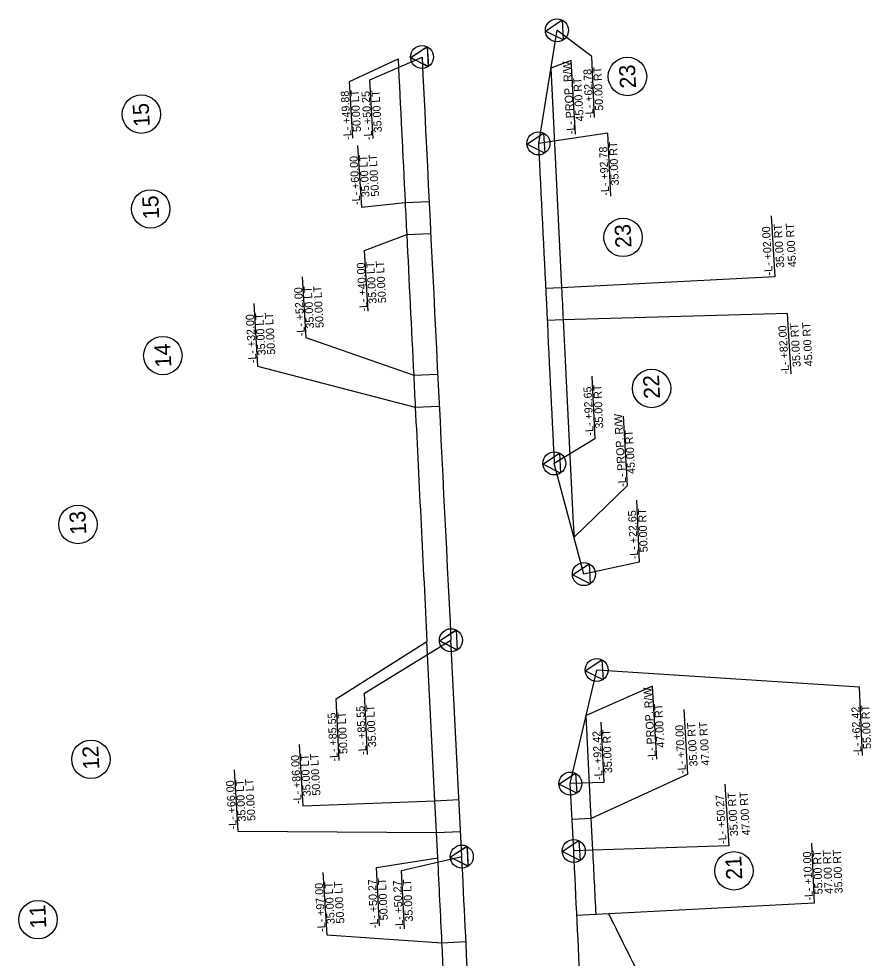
# Model space of a CAD drawing. Extents: x 2368169 to 2369183, y 801414 to 808542.
# Drawn here: x 2368559 to 2369092, y 803014 to 803601 of the extents above; entities that cross this region are included whole.
import ezdxf

# ---------------------------------------------------------------- set-up
doc = ezdxf.new("R2010")
doc.units = 0
for name, color, linetype in [('Prop Easement Construction', 7, 'Continuous'), ('Prop Easement Construction Station Offsets', 7, 'Continuous'), ('Prop Easement Permanent Drainage', 7, 'Continuous'), ('Prop Easement Permanent Drainage Station Offsets', 7, 'Continuous'), ('Prop Easement Permanent Drainage Utility', 7, 'Continuous'), ('Prop Easement Permanent Drainage Utility Station Offsets', 7, 'Continuous'), ('Prop Easement Permanent Utility', 7, 'Continuous'), ('Prop Easement Permanent Utility Station Offsets', 7, 'Continuous'), ('Prop Parcel Number CELL', 7, 'Continuous'), ('Prop Parcel Number Text', 7, 'Continuous'), ('Prop ROW Marker CELL', 7, 'Continuous'), ('Prop ROW RW Lines', 7, 'Continuous'), ('Prop ROW Station Offsets', 7, 'Continuous')]:
    doc.layers.add(name, color=color, linetype=linetype)

msp = doc.modelspace()

# ---------------------------------------------------------------- linework, layer by layer
at = {"layer": 'Prop Easement Construction'}
msp.add_line((2368916.67, 803101.18), (2368913.44, 803165.51), dxfattribs=at)
for centre, radius, start, end in [((2677047.33, 818679.94), 308526.21, 182.8071824, 182.8327013), ((2677047.33, 818679.94), 308526.21, 182.8364149, 182.8616691), ((2343687.36, 801815.32), 25262.05, 2.781389, 2.872893)]:
    msp.add_arc(centre, radius, start, end, dxfattribs=at)
at = {"layer": 'Prop Easement Construction Station Offsets'}
for points in [[(2368906.85, 803528.48), (2368904.06, 803574.6), (2368891.35, 803569.88)], [(2368936.52, 803352.45), (2368939.16, 803308.95), (2368905.86, 803276.84)], [(2368957.57, 803138.15), (2368954.8, 803183.74), (2368913.44, 803165.51)]]:
    msp.add_lwpolyline(points, dxfattribs=at)
at = {"layer": 'Prop Easement Permanent Drainage'}
for p, q in [((2368898.11, 803432.63), (2368888.12, 803432.14)), ((2368899.1, 803412.66), (2368889.11, 803412.16)), ((2368916.67, 803101.18), (2368904.69, 803100.57)), ((2368917.66, 803081.47), (2368916.67, 803101.18)), ((2368917.66, 803081.47), (2368905.68, 803080.87)), ((2368927.64, 803041.56), (2368907.66, 803040.59))]:
    msp.add_line(p, q, dxfattribs=at)
for centre, radius, start, end in [((2677047.33, 818679.94), 308526.21, 182.8327013, 182.8364149), ((2333618.27, 785468.75), 39440.53, 26.379142, 26.458672)]:
    msp.add_arc(centre, radius, start, end, dxfattribs=at)
at = {"layer": 'Prop Easement Permanent Drainage Station Offsets'}
for p, q in [((2369029.03, 803477.59), (2369031.33, 803439.43)), ((2369031.33, 803439.43), (2368898.11, 803432.63)), ((2368977.01, 803128.78), (2368974.58, 803169.22)), ((2368977.01, 803128.78), (2368916.67, 803101.18)), ((2369000.18, 803122.68), (2369002.5, 803084.13)), ((2369002.5, 803084.13), (2368917.66, 803081.47)), ((2369054.13, 803085.79), (2369055.96, 803048.33)), ((2369055.96, 803048.33), (2368927.64, 803041.56))]:
    msp.add_line(p, q, dxfattribs=at)
msp.add_lwpolyline([(2369041.5, 803378.85), (2369039.23, 803416.58), (2368899.1, 803412.66)], dxfattribs=at)
at = {"layer": 'Prop Easement Permanent Drainage Utility'}
for p, q in [((2368800.37, 803485.87), (2368815.35, 803486.61)), ((2368801.35, 803465.9), (2368816.33, 803466.63)), ((2368805.7, 803377.99), (2368820.68, 803378.73)), ((2368806.7, 803358.01), (2368821.68, 803358.75)), ((2368818.99, 803112.29), (2368833.97, 803113.05)), ((2368819.99, 803092.32), (2368818.99, 803112.29)), ((2368819.99, 803092.32), (2368834.98, 803093.07)), ((2368823.39, 803023.51), (2368838.37, 803024.23))]:
    msp.add_line(p, q, dxfattribs=at)
for centre, radius, start, end in [((2677047.33, 818679.94), 308621.21, 182.8219318, 182.8256454), ((2677047.33, 818679.94), 308621.21, 182.8419854, 182.845699), ((2343687.36, 801815.32), 25165.05, 2.706404, 2.75185)]:
    msp.add_arc(centre, radius, start, end, dxfattribs=at)
at = {"layer": 'Prop Easement Permanent Drainage Utility Station Offsets'}
for points in [[(2368770.71, 803521.54), (2368773.03, 803482.92), (2368800.37, 803485.87)], [(2368777.36, 803418.11), (2368775.09, 803455.86), (2368801.35, 803465.9)], [(2368736.09, 803439.51), (2368738.37, 803401.57), (2368805.7, 803377.99)], [(2368705.83, 803422.73), (2368708.18, 803383.67), (2368806.7, 803358.01)], [(2368734.07, 803147.38), (2368736.37, 803109.12), (2368818.99, 803112.29)], [(2368693.48, 803131.54), (2368695.78, 803093.28), (2368819.99, 803092.32)], [(2368749.02, 803067.51), (2368751.37, 803028.45), (2368823.39, 803023.51)]]:
    msp.add_lwpolyline(points, dxfattribs=at)
at = {"layer": 'Prop Easement Permanent Utility'}
for p, q in [((2368818.99, 803112.29), (2368814, 803211.71)), ((2368820.78, 803076.61), (2368819.99, 803092.32))]:
    msp.add_line(p, q, dxfattribs=at)
for centre, radius, start, end in [((2677047.33, 818679.94), 308621.21, 182.8052436, 182.8219318), ((2677047.33, 818679.94), 308621.21, 182.8256454, 182.8419854), ((2677047.33, 818679.94), 308621.21, 182.845699, 182.8728926), ((2343687.36, 801815.32), 25165.05, 2.75185, 2.872893)]:
    msp.add_arc(centre, radius, start, end, dxfattribs=at)
at = {"layer": 'Prop Easement Permanent Utility Station Offsets'}
for p, q in [((2368765.55, 803561.44), (2368795.95, 803575.66)), ((2368767.68, 803526.06), (2368765.55, 803561.44)), ((2368757.21, 803175.81), (2368814, 803211.71)), ((2368759.08, 803137.45), (2368757.21, 803175.81))]:
    msp.add_line(p, q, dxfattribs=at)
msp.add_lwpolyline([(2368784.34, 803034.08), (2368782.56, 803070.56), (2368820.78, 803076.61)], dxfattribs=at)
at = {"layer": 'Prop Parcel Number CELL'}
for p, q in [((2368939.26, 803564.6), (2368939.26, 803564.6)), ((2368635.62, 803541.07), (2368635.62, 803541.07)), ((2368641.47, 803481.9), (2368641.47, 803481.9)), ((2368936.54, 803464.08), (2368936.54, 803464.08)), ((2368649.01, 803390.3), (2368649.01, 803390.3)), ((2368954.34, 803369.74), (2368954.34, 803369.74)), ((2368595.94, 803284.8), (2368595.94, 803284.8)), ((2368604.08, 803138.12), (2368604.08, 803138.12)), ((2369005.75, 803068.47), (2369005.75, 803068.47)), ((2368571.03, 803037.97), (2368571.03, 803037.97))]:
    msp.add_line(p, q, dxfattribs=at)
for centre in [(2368939.26, 803564.6), (2368635.62, 803541.07), (2368641.47, 803481.9), (2368936.54, 803464.08), (2368649.01, 803390.3), (2368954.34, 803369.74), (2368595.94, 803284.8), (2368604.08, 803138.12), (2369005.75, 803068.47), (2368571.03, 803037.97)]:
    msp.add_circle(centre, 12, dxfattribs=at)
at = {"layer": 'Prop ROW Marker CELL'}
for p, q in [((2368895.2, 803593.43), (2368895.2, 803593.43)), ((2368895.2, 803593.43), (2368895.2, 803593.43)), ((2368810.92, 803576.76), (2368810.92, 803576.76)), ((2368810.92, 803576.76), (2368810.92, 803576.76)), ((2368883.65, 803522.8), (2368883.65, 803522.8)), ((2368883.65, 803522.8), (2368883.65, 803522.8)), ((2368893.55, 803322.93), (2368893.55, 803322.93)), ((2368893.55, 803322.93), (2368893.55, 803322.93)), ((2368912.02, 803253.78), (2368912.02, 803253.78)), ((2368912.02, 803253.78), (2368912.02, 803253.78)), ((2368828.98, 803212.47), (2368828.98, 803212.47)), ((2368828.98, 803212.47), (2368828.98, 803212.47)), ((2368920.03, 803193.88), (2368920.03, 803193.88)), ((2368920.03, 803193.88), (2368920.03, 803193.88)), ((2368903.56, 803122.97), (2368903.56, 803122.97)), ((2368903.56, 803122.97), (2368903.56, 803122.97)), ((2368905.68, 803080.87), (2368905.68, 803080.87)), ((2368905.68, 803080.87), (2368905.68, 803080.87)), ((2368835.76, 803077.36), (2368835.76, 803077.36)), ((2368835.76, 803077.36), (2368835.76, 803077.36))]:
    msp.add_line(p, q, dxfattribs=at)
for points in [[(2368899.17, 803587.41), (2368888.02, 803593), (2368898.42, 803599.89)], [(2368899.17, 803587.41), (2368888.02, 803593), (2368898.42, 803599.89)], [(2368814.8, 803570.68), (2368803.72, 803576.44), (2368814.23, 803583.17)], [(2368814.89, 803570.74), (2368803.73, 803576.33), (2368814.14, 803583.22)], [(2368887.62, 803516.77), (2368876.46, 803522.36), (2368886.87, 803529.25)], [(2368887.62, 803516.77), (2368876.46, 803522.36), (2368886.87, 803529.25)], [(2368897.52, 803316.91), (2368886.36, 803322.5), (2368896.76, 803329.39)], [(2368897.52, 803316.91), (2368886.36, 803322.5), (2368896.76, 803329.39)], [(2368915.99, 803247.75), (2368904.83, 803253.34), (2368915.24, 803260.23)], [(2368915.99, 803247.75), (2368904.83, 803253.34), (2368915.24, 803260.23)], [(2368832.86, 803206.38), (2368821.79, 803212.14), (2368832.3, 803218.87)], [(2368832.95, 803206.44), (2368821.8, 803212.03), (2368832.2, 803218.92)], [(2368924, 803187.86), (2368912.84, 803193.45), (2368923.25, 803200.33)], [(2368924, 803187.86), (2368912.84, 803193.45), (2368923.25, 803200.33)], [(2368907.53, 803116.94), (2368896.38, 803122.53), (2368906.78, 803129.42)], [(2368907.53, 803116.94), (2368896.38, 803122.53), (2368906.78, 803129.42)], [(2368909.64, 803074.85), (2368898.49, 803080.44), (2368908.89, 803087.32)], [(2368909.64, 803074.85), (2368898.49, 803080.44), (2368908.89, 803087.32)], [(2368839.64, 803071.28), (2368828.57, 803077.04), (2368839.08, 803083.77)], [(2368839.73, 803071.34), (2368828.58, 803076.93), (2368838.98, 803083.81)]]:
    msp.add_lwpolyline(points, close=True, dxfattribs=at)
for centre in [(2368895.2, 803593.43), (2368810.92, 803576.76), (2368883.65, 803522.8), (2368893.55, 803322.93), (2368912.02, 803253.78), (2368828.98, 803212.47), (2368920.03, 803193.88), (2368903.56, 803122.97), (2368905.68, 803080.87), (2368835.76, 803077.36)]:
    msp.add_circle(centre, 7.2, dxfattribs=at)
at = {"layer": 'Prop ROW RW Lines'}
for p, q in [((2368895.2, 803593.43), (2368883.65, 803522.8)), ((2368912.02, 803253.78), (2368893.55, 803322.93)), ((2368835.76, 803077.36), (2368828.98, 803212.47)), ((2368903.56, 803122.97), (2368920.03, 803193.88)), ((2368905.68, 803080.87), (2368903.56, 803122.97))]:
    msp.add_line(p, q, dxfattribs=at)
for centre, radius, start, end in [((2677047.33, 818679.94), 308606.21, 182.8051748, 182.8728926), ((2677047.33, 818679.94), 308536.21, 182.8158452, 182.8530055), ((2343687.36, 801815.32), 25250.05, 2.472411, 2.872893), ((2343687.36, 801815.32), 25180.05, 2.472411, 2.872893)]:
    msp.add_arc(centre, radius, start, end, dxfattribs=at)
at = {"layer": 'Prop ROW Station Offsets'}
for p, q in [((2368926.81, 803529.15), (2368883.65, 803522.8)), ((2368926.81, 803529.15), (2368928.58, 803489.85)), ((2369084.14, 803183.2), (2368920.03, 803193.88)), ((2369086.06, 803140.55), (2369084.14, 803183.2)), ((2368922.71, 803161.22), (2368924.4, 803123.61)), ((2368924.4, 803123.61), (2368903.56, 803122.97))]:
    msp.add_line(p, q, dxfattribs=at)
for points in [[(2368918.69, 803538.99), (2368916.97, 803577.1), (2368895.2, 803593.43)], [(2368780.48, 803525.9), (2368778.28, 803562.48), (2368810.92, 803576.76)], [(2368917.04, 803377.36), (2368918.8, 803338.38), (2368893.55, 803322.93)], [(2368944.89, 803300.04), (2368946.63, 803261.24), (2368912.02, 803253.78)], [(2368776.93, 803141.18), (2368775.06, 803179.53), (2368828.98, 803212.47)], [(2368799.89, 803032.22), (2368798.11, 803068.7), (2368835.76, 803077.36)]]:
    msp.add_lwpolyline(points, dxfattribs=at)

# ---------------------------------------------------------------- texts
at = {"layer": 'Prop Easement Construction Station Offsets'}
for s, p in [('-L- PROP. R/W', (2368906.47, 803528.67)), ('45.00 RT', (2368912, 803536.67)), ('-L- PROP. R/W', (2368938.59, 803308.48)), ('45.00 RT', (2368944.12, 803316.48)), ('-L- PROP. R/W', (2368956.99, 803137.55)), ('47.00 RT', (2368962.51, 803145.55))]:
    msp.add_text(s, height=5, rotation=93.47163, dxfattribs=at).set_placement(p)
at = {"layer": 'Prop Easement Permanent Drainage Station Offsets'}
for s, rotation, p in [('-L- +02.00', 93.44297, (2369030.01, 803440.49)), ('35.00 RT', 93.44297, (2369037.24, 803445.18)), ('45.00 RT', 93.44297, (2369044.73, 803445.63)), ('35.00 RT', 93.44297, (2369047.5, 803383.31)), ('45.00 RT', 93.44297, (2369054.98, 803383.76)), ('-L- +82.00', 93.44297, (2369040.26, 803378.63)), ('-L- +70.00', 93.44297, (2368975.84, 803129.14)), ('35.00 RT', 93.44297, (2368983.08, 803133.82)), ('47.00 RT', 93.44297, (2368990.56, 803134.28)), ('35.00 RT', 93.44297, (2369008.4, 803090.25)), ('47.00 RT', 93.44297, (2369015.88, 803090.7)), ('-L- +50.27', 93.44297, (2369001.17, 803085.45)), ('55.00 RT', 92.56453, (2369061.23, 803053.9)), ('47.00 RT', 92.56453, (2369067.47, 803054.18)), ('35.00 RT', 92.56453, (2369073.72, 803054.46)), ('-L- +10.00', 92.56453, (2369055.15, 803049.98))]:
    msp.add_text(s, height=5, rotation=rotation, dxfattribs=at).set_placement(p)
at = {"layer": 'Prop Easement Permanent Drainage Utility Station Offsets'}
for s, p in [('35.00 LT', (2368778.15, 803489.38)), ('50.00 LT', (2368784.14, 803489.74)), ('-L- +60.00', (2368772.43, 803484.49)), ('-L- +40.00', (2368776.87, 803417.93)), ('35.00 LT', (2368782.59, 803422.82)), ('50.00 LT', (2368788.58, 803423.18)), ('35.00 LT', (2368743.53, 803407.35)), ('50.00 LT', (2368749.52, 803407.71)), ('-L- +52.00', (2368737.82, 803402.46)), ('-L- +32.00', (2368707.56, 803385.68)), ('35.00 LT', (2368713.27, 803390.57)), ('50.00 LT', (2368719.26, 803390.93)), ('-L- +86.00', (2368735.8, 803110.33)), ('35.00 LT', (2368741.52, 803115.22)), ('50.00 LT', (2368747.5, 803115.58)), ('-L- +66.00', (2368695.21, 803094.49)), ('35.00 LT', (2368700.92, 803099.38)), ('50.00 LT', (2368706.91, 803099.74)), ('-L- +97.00', (2368750.75, 803030.46)), ('35.00 LT', (2368756.47, 803035.35)), ('50.00 LT', (2368762.46, 803035.71))]:
    msp.add_text(s, height=5, rotation=93.44297, dxfattribs=at).set_placement(p)
at = {"layer": 'Prop Easement Permanent Utility Station Offsets'}
for s, rotation, p in [('-L- +49.88', 93.44297, (2368766.89, 803525.2)), ('50.00 LT', 93.44297, (2368772.86, 803530.1)), ('-L- +85.55', 92.79291, (2368758.37, 803136.84)), ('50.00 LT', 92.79291, (2368764.39, 803141.57)), ('50.00 LT', 92.79291, (2368789.61, 803037.72)), ('-L- +50.27', 92.79291, (2368783.59, 803032.77))]:
    msp.add_text(s, height=5, rotation=rotation, dxfattribs=at).set_placement(p)
at = {"layer": 'Prop Parcel Number Text'}
for s, rotation, p in [('23', 92.99787, (2368944.64, 803557.42)), ('15', 93.44297, (2368640.94, 803533.42)), ('15', 92.79291, (2368646.77, 803475.63)), ('23', 92.79291, (2368941.84, 803457.79)), ('14', 92.79291, (2368654.36, 803383.13)), ('22', 92.79291, (2368959.64, 803363.54)), ('13', 92.79291, (2368601.24, 803278.58)), ('12', 92.79291, (2368609.37, 803131.94)), ('21', 92.79291, (2369011.01, 803063.21)), ('11', 92.79291, (2368576.28, 803032.7))]:
    msp.add_text(s, height=10, rotation=rotation, dxfattribs=at).set_placement(p)
at = {"layer": 'Prop ROW Station Offsets'}
for s, rotation, p in [('-L- +62.78', 92.57642, (2368918.07, 803538.78)), ('50.00 RT', 92.57642, (2368924.12, 803543.29)), ('-L- +50.25', 93.44297, (2368779.9, 803525.04)), ('35.00 LT', 93.44297, (2368785.88, 803529.84)), ('35.00 RT', 92.57642, (2368933.91, 803496.64)), ('-L- +92.78', 92.57642, (2368927.88, 803490.28)), ('-L- +92.65', 92.57642, (2368918.08, 803340.42)), ('35.00 RT', 92.57642, (2368924.14, 803344.84)), ('-L- +22.65', 92.57642, (2368945.92, 803263.14)), ('50.00 RT', 92.57642, (2368951.98, 803267.56)), ('-L- +85.55', 92.79291, (2368776.31, 803141.02)), ('35.00 LT', 92.79291, (2368782.33, 803145.76)), ('-L- +62.42', 92.57642, (2369085.44, 803140.45)), ('55.00 RT', 92.57642, (2369091.5, 803144.7)), ('-L- +92.42', 92.57642, (2368923.7, 803125.33)), ('35.00 RT', 92.57642, (2368929.76, 803129.57)), ('-L- +50.27', 92.79291, (2368799.28, 803031.95)), ('35.00 LT', 92.79291, (2368805.29, 803036.9))]:
    msp.add_text(s, height=5, rotation=rotation, dxfattribs=at).set_placement(p)

doc.saveas('drawing.dxf')
